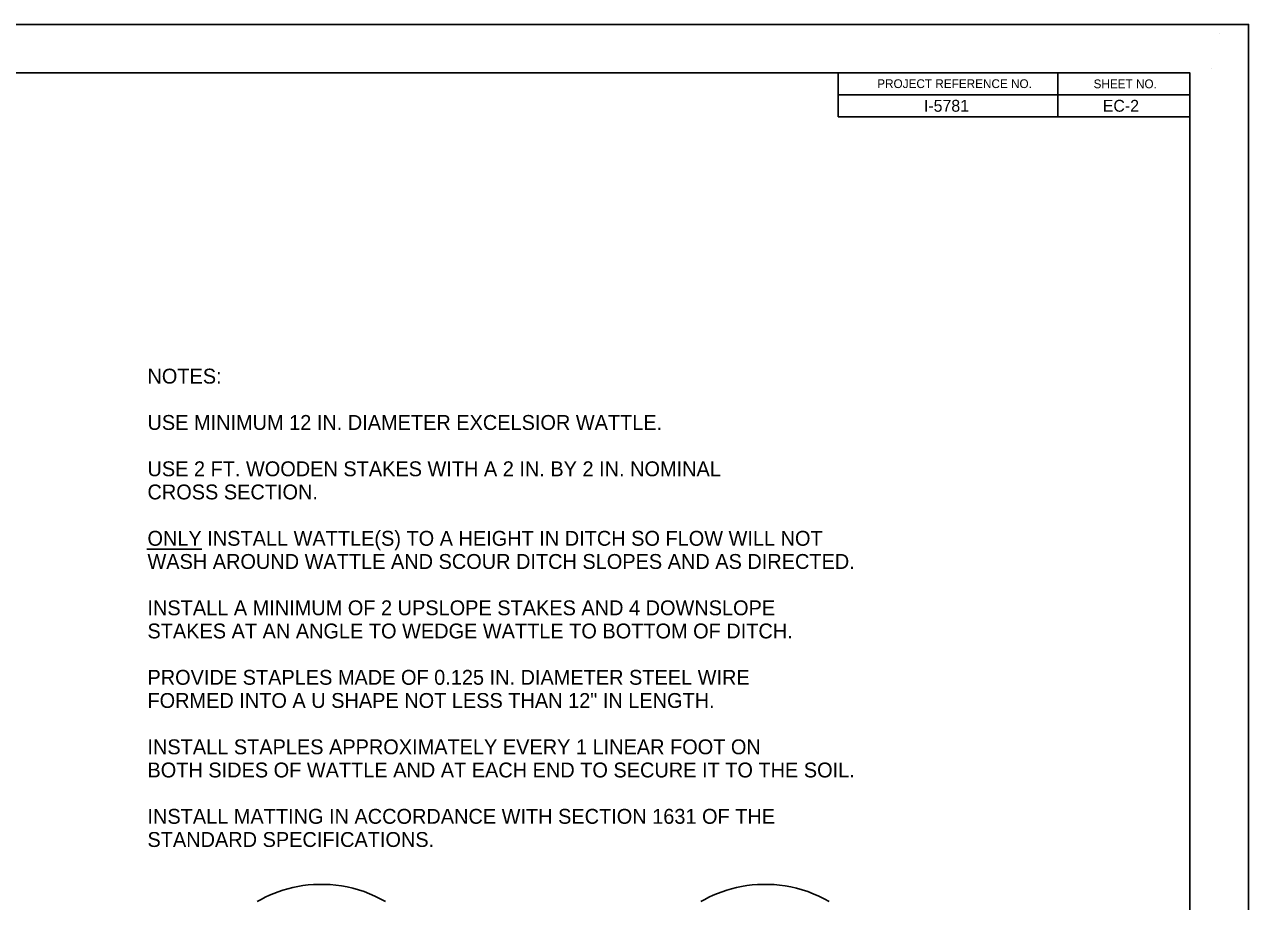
# Model space of a CAD drawing. Extents: x 8096 to 9796, y 9620 to 10720.
# Drawn here: x 9099 to 9796, y 10220 to 10720 of the extents above; entities that cross this region are included whole.
import ezdxf

# ---------------------------------------------------------------- set-up
doc = ezdxf.new("R2010")
doc.units = 0
for name, color, linetype in [('Blank Plan Sheet Both CELL', 7, 'Continuous'), ('Default', 7, 'Continuous'), ('Old_Level_1', 7, 'Continuous'), ('Sheet Plot Border Outside CELL', 7, 'Continuous')]:
    doc.layers.add(name, color=color, linetype=linetype)

msp = doc.modelspace()

# ---------------------------------------------------------------- linework, layer by layer
at = {"layer": 'Blank Plan Sheet Both CELL'}
for p, q in [((9779.02, 10714.83), (9779.02, 10714.83)), ((9687.02, 10692.28), (9687.02, 10667.29)), ((9774.52, 10694.83), (9774.52, 10694.83)), ((9561.97, 10679.78), (9762.02, 10679.78)), ((9561.97, 10667.28), (9762.02, 10667.28)), ((9561.97, 10667.28), (9762.02, 10667.28))]:
    msp.add_line(p, q, dxfattribs=at)
for points in [[(9762.02, 10692.33), (8262.02, 10692.33), (8262.02, 9642.33), (9762.02, 9642.33)], [(9561.97, 10692.33), (9762.02, 10692.33), (9762.02, 10667.28), (9561.97, 10667.28)]]:
    msp.add_lwpolyline(points, close=True, dxfattribs=at)
at = {"layer": 'Default'}
msp.add_line((9168.4, 10421), (9199.73, 10421), dxfattribs=at)
for points in [[(9254.32, 10229.02), (9251.44, 10228.42)], [(9257.27, 10229.51), (9254.32, 10229.02)], [(9260.28, 10229.88), (9257.27, 10229.51)], [(9263.35, 10230.13), (9260.28, 10229.88)], [(9266.46, 10230.25), (9263.35, 10230.13)], [(9269.61, 10230.23), (9266.46, 10230.25)], [(9272.8, 10230.08), (9269.61, 10230.23)], [(9276, 10229.79), (9272.8, 10230.08)], [(9279.22, 10229.35), (9276, 10229.79)], [(9282.44, 10228.76), (9279.22, 10229.35)], [(9285.66, 10228.02), (9282.44, 10228.76)], [(9506.93, 10229.02), (9504.05, 10228.42)], [(9509.88, 10229.51), (9506.93, 10229.02)], [(9512.9, 10229.88), (9509.88, 10229.51)], [(9515.96, 10230.13), (9512.9, 10229.88)], [(9519.07, 10230.25), (9515.96, 10230.13)], [(9522.22, 10230.23), (9519.07, 10230.25)], [(9525.41, 10230.08), (9522.22, 10230.23)], [(9528.61, 10229.79), (9525.41, 10230.08)], [(9531.83, 10229.35), (9528.61, 10229.79)], [(9535.05, 10228.76), (9531.83, 10229.35)], [(9538.27, 10228.02), (9535.05, 10228.76)], [(9235.74, 10222.89), (9233.42, 10221.71)], [(9238.15, 10224.01), (9235.74, 10222.89)], [(9240.64, 10225.06), (9238.15, 10224.01)], [(9243.22, 10226.03), (9240.64, 10225.06)], [(9245.88, 10226.92), (9243.22, 10226.03)], [(9248.62, 10227.72), (9245.88, 10226.92)], [(9251.44, 10228.42), (9248.62, 10227.72)], [(9288.86, 10227.13), (9285.66, 10228.02)], [(9292.03, 10226.09), (9288.86, 10227.13)], [(9295.17, 10224.9), (9292.03, 10226.09)], [(9298.25, 10223.57), (9295.17, 10224.9)], [(9301.28, 10222.09), (9298.25, 10223.57)], [(9304.24, 10220.47), (9301.28, 10222.09)], [(9488.35, 10222.89), (9486.03, 10221.71)], [(9490.76, 10224.01), (9488.35, 10222.89)], [(9493.26, 10225.06), (9490.76, 10224.01)], [(9495.83, 10226.03), (9493.26, 10225.06)], [(9498.5, 10226.92), (9495.83, 10226.03)], [(9501.23, 10227.72), (9498.5, 10226.92)], [(9504.05, 10228.42), (9501.23, 10227.72)], [(9541.47, 10227.13), (9538.27, 10228.02)], [(9544.64, 10226.09), (9541.47, 10227.13)], [(9547.78, 10224.9), (9544.64, 10226.09)], [(9550.86, 10223.57), (9547.78, 10224.9)], [(9553.89, 10222.09), (9550.86, 10223.57)], [(9556.85, 10220.47), (9553.89, 10222.09)], [(9233.42, 10221.71), (9231.18, 10220.47)], [(9486.03, 10221.71), (9483.79, 10220.47)]]:
    msp.add_lwpolyline(points, dxfattribs=at)
at = {"layer": 'Sheet Plot Border Outside CELL'}
msp.add_lwpolyline([(8095.52, 9619.83), (9795.52, 9619.83), (9795.52, 10719.83), (8095.52, 10719.83)], close=True, dxfattribs=at)

# ---------------------------------------------------------------- texts
at = {"layer": 'Blank Plan Sheet Both CELL'}
for s, height, p in [('PROJECT REFERENCE NO.', 5.0001, (9584.17, 10683.63)), ('SHEET NO.', 5, (9707.32, 10683.53))]:
    msp.add_text(s, height=height, rotation=360, dxfattribs=at).set_placement(p)
at = {"layer": 'Default'}
for s, p in [('I-5781', (9610.75, 10670.15)), ('EC-2', (9712.56, 10670.15))]:
    msp.add_text(s, height=6.769, dxfattribs=at).set_placement(p)
at = {"layer": 'Old_Level_1'}
for s, height, p in [('NOTES:', 8.48, (9168.75, 10515.37)), ('USE MINIMUM 12 IN. DIAMETER EXCELSIOR WATTLE.', 8.4804, (9168.75, 10488.99)), ('USE 2 FT. WOODEN STAKES WITH A 2 IN. BY 2 IN. NOMINAL', 8.4804, (9168.75, 10462.61)), ('CROSS SECTION.', 8.4804, (9168.75, 10449.42)), ('ONLY INSTALL WATTLE(S) TO A HEIGHT IN DITCH SO FLOW WILL NOT', 8.4804, (9168.75, 10423.03)), ('WASH AROUND WATTLE AND SCOUR DITCH SLOPES AND AS DIRECTED.', 8.4804, (9168.75, 10409.84)), ('INSTALL A MINIMUM OF 2 UPSLOPE STAKES AND 4 DOWNSLOPE', 8.4804, (9168.75, 10383.46)), ('STAKES AT AN ANGLE TO WEDGE WATTLE TO BOTTOM OF DITCH.', 8.4804, (9168.75, 10370.27)), ('PROVIDE STAPLES MADE OF 0.125 IN. DIAMETER STEEL WIRE', 8.4804, (9168.75, 10343.88)), ('FORMED INTO A U SHAPE NOT LESS THAN 12" IN LENGTH.', 8.4804, (9168.75, 10330.69)), ('INSTALL STAPLES APPROXIMATELY EVERY 1 LINEAR FOOT ON', 8.4804, (9168.75, 10304.31)), ('BOTH SIDES OF WATTLE AND AT EACH END TO SECURE IT TO THE SOIL.', 8.4804, (9168.75, 10291.12)), ('INSTALL MATTING IN ACCORDANCE WITH SECTION 1631 OF THE', 8.4804, (9168.75, 10264.73)), ('STANDARD SPECIFICATIONS.', 8.4804, (9168.75, 10251.54))]:
    msp.add_text(s, height=height, dxfattribs=at).set_placement(p)

doc.saveas('drawing.dxf')
